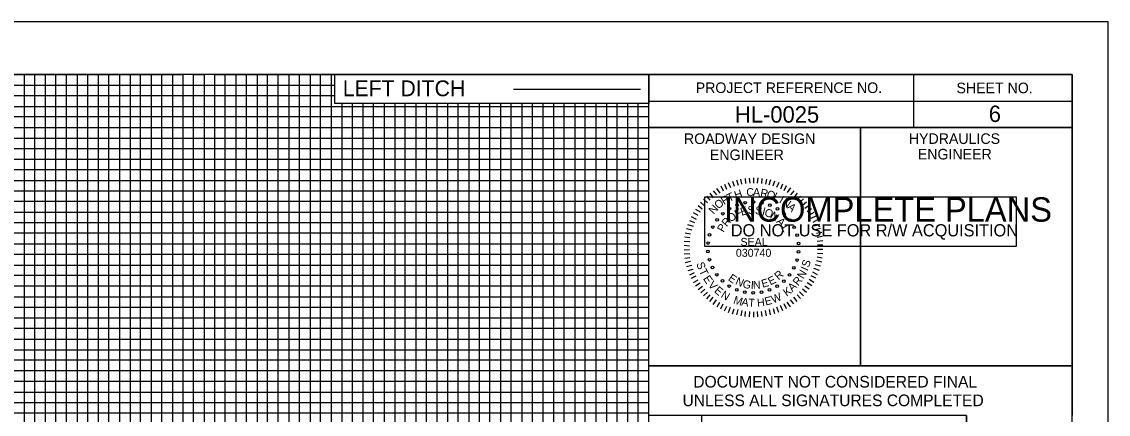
# Model space of a CAD drawing. Extents: x 1524869 to 1526553, y 501099 to 502199.
# Drawn here: x 1526040 to 1526553, y 502013 to 502199 of the extents above; entities that cross this region are included whole.
import ezdxf

# ---------------------------------------------------------------- set-up
doc = ezdxf.new("R2010")
doc.units = 0
for name, color, linetype in [('Old_Level_9', 7, 'Continuous'), ('Prop Grid Mask', 7, 'Continuous'), ('Sheet Data Field CELL', 7, 'Continuous'), ('Sheet Layout Profile Border Port 1', 7, 'Continuous'), ('Sheet Plot Border Outside CELL', 7, 'Continuous'), ('Sheet Profile CELL', 7, 'Continuous'), ('Sheet Profile Grid Major CELL', 7, 'Continuous'), ('Sheet Profile Grid Middle CELL', 7, 'Continuous'), ('Sheet Profile Grid Minor CELL', 7, 'Continuous'), ('Sheet Sticker Exception Certification CELL', 7, 'Continuous'), ('Sheet Sticker Incomplete CELL', 7, 'Continuous')]:
    doc.layers.add(name, color=color, linetype=linetype)

msp = doc.modelspace()

# ---------------------------------------------------------------- linework, layer by layer
at = {"layer": 'Old_Level_9'}
for p, q in [((1526272.11, 502166.74), (1526332.11, 502166.74)), ((1526377.53, 502123.79), (1526378.23, 502121.29)), ((1526379.43, 502124.19), (1526379.93, 502121.79)), ((1526381.53, 502124.49), (1526381.73, 502122.09)), ((1526383.43, 502124.59), (1526383.73, 502122.19)), ((1526385.53, 502124.79), (1526385.53, 502122.19)), ((1526387.63, 502124.79), (1526387.33, 502122.19)), ((1526389.53, 502124.49), (1526389.33, 502122.09)), ((1526391.63, 502124.19), (1526391.13, 502121.79)), ((1526393.53, 502123.79), (1526392.83, 502121.39)), ((1526366.53, 502118.69), (1526368.03, 502116.69)), ((1526368.13, 502119.79), (1526369.63, 502117.59)), ((1526370.03, 502120.99), (1526371.23, 502118.59)), ((1526371.83, 502121.79), (1526372.73, 502119.49)), ((1526373.53, 502122.59), (1526374.73, 502120.19)), ((1526375.63, 502123.19), (1526376.33, 502120.79)), ((1526395.43, 502123.19), (1526394.73, 502120.79)), ((1526397.53, 502122.59), (1526396.33, 502120.19)), ((1526399.23, 502121.79), (1526398.33, 502119.49)), ((1526401.03, 502120.99), (1526399.83, 502118.59)), ((1526402.93, 502119.99), (1526401.43, 502117.79)), ((1526404.53, 502118.69), (1526403.03, 502116.69)), ((1526360.53, 502113.29), (1526362.43, 502111.59)), ((1526361.93, 502114.69), (1526363.73, 502112.99)), ((1526363.33, 502116.19), (1526364.93, 502114.29)), ((1526364.93, 502117.49), (1526366.53, 502115.39)), ((1526406.13, 502117.49), (1526404.53, 502115.49)), ((1526407.73, 502116.19), (1526406.13, 502114.39)), ((1526409.13, 502114.89), (1526407.33, 502112.99)), ((1526410.53, 502113.29), (1526408.63, 502111.69)), ((1526357.03, 502108.39), (1526359.23, 502107.09)), ((1526358.13, 502109.99), (1526360.33, 502108.69)), ((1526359.43, 502111.69), (1526361.33, 502110.09)), ((1526411.83, 502111.69), (1526409.73, 502110.29)), ((1526412.93, 502110.09), (1526410.83, 502108.69)), ((1526414.03, 502108.39), (1526411.83, 502107.09)), ((1526354.43, 502102.79), (1526357.03, 502101.99)), ((1526355.23, 502104.69), (1526357.63, 502103.69)), ((1526356.03, 502106.49), (1526358.43, 502105.29)), ((1526415.03, 502106.59), (1526412.63, 502105.49)), ((1526415.83, 502104.89), (1526413.63, 502103.69)), ((1526416.63, 502102.79), (1526414.03, 502101.99)), ((1526353.33, 502098.79), (1526355.83, 502098.29)), ((1526353.83, 502100.89), (1526356.33, 502100.19)), ((1526417.23, 502100.89), (1526414.73, 502100.19)), ((1526417.73, 502098.99), (1526415.23, 502098.49)), ((1526352.73, 502092.89), (1526355.23, 502092.69)), ((1526352.83, 502094.79), (1526355.43, 502094.69)), ((1526353.03, 502096.89), (1526355.53, 502096.59)), ((1526418.03, 502097.09), (1526415.63, 502096.59)), ((1526418.23, 502094.99), (1526415.63, 502094.69)), ((1526418.33, 502092.89), (1526415.83, 502092.89)), ((1526352.73, 502090.79), (1526355.23, 502090.99)), ((1526352.83, 502088.79), (1526355.43, 502089.09)), ((1526418.33, 502090.99), (1526415.83, 502090.99)), ((1526418.23, 502088.89), (1526415.83, 502089.09)), ((1526353.03, 502086.79), (1526355.53, 502087.19)), ((1526353.33, 502084.79), (1526355.83, 502085.39)), ((1526353.93, 502082.89), (1526356.33, 502083.49)), ((1526417.23, 502082.99), (1526414.73, 502083.69)), ((1526417.73, 502084.89), (1526415.23, 502085.59)), ((1526418.03, 502086.79), (1526415.63, 502087.29)), ((1526354.63, 502080.99), (1526357.03, 502081.69)), ((1526355.43, 502078.99), (1526357.63, 502079.99)), ((1526356.23, 502077.29), (1526358.43, 502078.39)), ((1526415.03, 502077.29), (1526412.83, 502078.39)), ((1526415.83, 502078.99), (1526413.63, 502080.19)), ((1526416.63, 502080.99), (1526414.03, 502081.89)), ((1526357.13, 502075.39), (1526359.43, 502076.59)), ((1526358.13, 502073.79), (1526360.33, 502075.09)), ((1526359.43, 502071.99), (1526361.43, 502073.59)), ((1526360.63, 502070.39), (1526362.53, 502072.19)), ((1526410.53, 502070.59), (1526408.63, 502072.19)), ((1526411.83, 502072.19), (1526409.73, 502073.59)), ((1526413.13, 502073.79), (1526410.83, 502075.19)), ((1526414.03, 502075.39), (1526411.83, 502076.79)), ((1526361.93, 502068.99), (1526363.83, 502070.69)), ((1526363.53, 502067.59), (1526365.13, 502069.49)), ((1526364.93, 502066.29), (1526366.53, 502068.39)), ((1526366.53, 502064.99), (1526368.03, 502067.09)), ((1526404.53, 502065.19), (1526403.03, 502067.19)), ((1526406.23, 502066.29), (1526404.53, 502068.39)), ((1526407.73, 502067.69), (1526406.13, 502069.49)), ((1526409.13, 502068.99), (1526407.33, 502070.89)), ((1526368.33, 502063.89), (1526369.63, 502066.09)), ((1526370.03, 502062.89), (1526371.23, 502065.19)), ((1526371.83, 502061.99), (1526372.93, 502064.19)), ((1526373.73, 502061.19), (1526374.73, 502063.59)), ((1526375.63, 502060.49), (1526376.43, 502062.89)), ((1526377.73, 502060.09), (1526378.23, 502062.49)), ((1526379.63, 502059.59), (1526380.13, 502062.09)), ((1526381.53, 502059.29), (1526381.83, 502061.69)), ((1526383.63, 502059.09), (1526383.73, 502061.69)), ((1526387.63, 502059.09), (1526387.43, 502061.69)), ((1526389.63, 502059.29), (1526389.33, 502061.69)), ((1526391.73, 502059.59), (1526391.23, 502062.09)), ((1526393.63, 502060.09), (1526393.03, 502062.49)), ((1526395.53, 502060.49), (1526394.93, 502062.89)), ((1526397.53, 502061.19), (1526396.53, 502063.69)), ((1526399.43, 502061.99), (1526398.33, 502064.39)), ((1526401.13, 502062.89), (1526400.03, 502065.19)), ((1526402.93, 502063.89), (1526401.43, 502066.09)), ((1526385.73, 502058.99), (1526385.73, 502061.49))]:
    msp.add_line(p, q, dxfattribs=at)
for centre in [(1526381.58, 502113.03), (1526385.53, 502113.38), (1526389.48, 502113), (1526371.03, 502107.83), (1526374.2, 502110.2), (1526377.76, 502111.96), (1526393.29, 502111.9), (1526396.83, 502110.12), (1526399.98, 502107.71), (1526368.35, 502104.91), (1526402.64, 502104.77), (1526364.8, 502097.85), (1526366.25, 502101.54), (1526404.72, 502101.39), (1526406.13, 502097.69), (1526364.05, 502093.96), (1526406.85, 502093.79), (1526364.04, 502089.99), (1526406.83, 502089.82), (1526364.75, 502086.09), (1526366.17, 502082.39), (1526404.64, 502082.24), (1526406.09, 502085.93), (1526368.25, 502079.01), (1526402.54, 502078.87), (1526370.91, 502076.07), (1526374.06, 502073.66), (1526377.6, 502071.88), (1526393.13, 502071.82), (1526396.68, 502073.58), (1526399.86, 502075.95), (1526381.41, 502070.78), (1526385.36, 502070.4), (1526389.31, 502070.75)]:
    msp.add_circle(centre, 0.63, dxfattribs=at)
at = {"layer": 'Prop Grid Mask'}
for p, q in [((1526187.87, 502173.56), (1526336.08, 502173.56)), ((1526187.87, 502159.84), (1526187.87, 502173.56)), ((1526336.08, 502173.56), (1526336.08, 502159.84)), ((1526336.08, 502159.84), (1526187.87, 502159.84))]:
    msp.add_line(p, q, dxfattribs=at)
at = {"layer": 'Sheet Layout Profile Border Port 1'}
msp.add_lwpolyline([(1525086.08, 502173.56), (1525058.64, 501673.56), (1526486.08, 501673.56), (1526486.08, 502012.51), (1526336.03, 502012.51), (1526336.08, 502173.56)], close=True, dxfattribs=at)
msp.add_lwpolyline([(1525086.08, 502173.56), (1525058.64, 501673.56), (1526486.08, 501673.56), (1526486.08, 502012.51), (1526336.03, 502012.51), (1526336.08, 502173.56)], close=True, dxfattribs=at)
at = {"layer": 'Sheet Plot Border Outside CELL'}
msp.add_lwpolyline([(1524869.08, 501098.56), (1526553.08, 501098.56), (1526553.08, 502198.56), (1524869.08, 502198.56)], close=True, dxfattribs=at)
at = {"layer": 'Sheet Profile CELL'}
for p, q in [((1526461.08, 502173.51), (1526461.08, 502148.51)), ((1526336.03, 502161.01), (1526536.08, 502161.01)), ((1526436.08, 502148.51), (1526436.08, 502036.06))]:
    msp.add_line(p, q, dxfattribs=at)
for points in [[(1526536.08, 502173.56), (1525036.08, 502173.56), (1525036.08, 501123.56), (1526536.08, 501123.56)], [(1526336.03, 502173.56), (1526536.08, 502173.56), (1526536.08, 502148.51), (1526336.03, 502148.51)], [(1526336.03, 502148.51), (1526436.08, 502148.51), (1526436.08, 502036.01), (1526336.03, 502036.01)], [(1526436.08, 502148.51), (1526536.08, 502148.51), (1526536.08, 502036.01), (1526436.08, 502036.01)]]:
    msp.add_lwpolyline(points, close=True, dxfattribs=at)
at = {"layer": 'Sheet Profile Grid Major CELL'}
for points in [[(1526036.08, 502173.56), (1526086.08, 502173.56), (1526086.08, 501673.56), (1526136.08, 501673.56), (1526136.08, 502173.56), (1526186.08, 502173.56), (1526186.08, 501673.56), (1526236.08, 501673.56), (1526236.08, 502159.84)], [(1526286.08, 502159.84), (1526286.08, 501673.56), (1526336.08, 501673.56), (1526336.08, 502173.56), (1526362.38, 502173.56)], [(1525036.08, 502123.56), (1526336.08, 502123.56)], [(1526336.08, 502073.56), (1525036.08, 502073.56), (1525036.08, 502023.56), (1526336.08, 502023.56)], [(1526486.08, 502012.51), (1526486.08, 501673.56), (1526536.08, 501673.56), (1526536.08, 502023.56)]]:
    msp.add_lwpolyline(points, dxfattribs=at)
at = {"layer": 'Sheet Profile Grid Middle CELL'}
msp.add_line((1525036.08, 502148.56), (1526336.03, 502148.56), dxfattribs=at)
for points in [[(1526011.08, 501673.56), (1526061.08, 501673.56), (1526061.08, 502173.56), (1526111.08, 502173.56), (1526111.08, 501673.56), (1526161.08, 501673.56), (1526161.08, 502173.56), (1526211.08, 502173.56)], [(1526211.08, 502159.84), (1526211.08, 501673.56), (1526261.08, 501673.56), (1526261.08, 502159.84)], [(1526311.08, 502159.84), (1526311.08, 501673.56), (1526361.08, 501673.56), (1526361.08, 502012.51)], [(1526336.08, 502098.56), (1525036.08, 502098.56), (1525036.08, 502048.56), (1526336.08, 502048.56)]]:
    msp.add_lwpolyline(points, dxfattribs=at)
at = {"layer": 'Sheet Profile Grid Minor CELL'}
for p, q in [((1525086.08, 502168.56), (1526187.87, 502168.56)), ((1526187.87, 502163.52), (1525086.08, 502163.21)), ((1525086.08, 502158.56), (1526336.08, 502158.56)), ((1526336.03, 502038.56), (1525086.08, 502038.56)), ((1526336.08, 502033.56), (1525086.08, 502033.56)), ((1526336.08, 502028.56), (1525086.08, 502028.56)), ((1525086.08, 502018.56), (1526336.08, 502018.56)), ((1526336.08, 502013.56), (1525086.08, 502013.56))]:
    msp.add_line(p, q, dxfattribs=at)
for points in [[(1526031.08, 502173.56), (1526041.08, 502173.56), (1526041.08, 501673.56)], [(1526046.08, 501673.56), (1526046.08, 502173.56), (1526051.08, 502173.56), (1526051.08, 501673.56)], [(1526056.08, 501673.56), (1526056.08, 502173.56), (1526066.08, 502173.56), (1526066.08, 501673.56)], [(1526071.08, 501673.56), (1526071.08, 502173.56), (1526076.08, 502173.56), (1526076.08, 501673.56)], [(1526081.08, 501673.56), (1526081.08, 502173.56), (1526091.08, 502173.56), (1526091.08, 501673.56)], [(1526096.08, 501673.56), (1526096.08, 502173.56), (1526101.08, 502173.56), (1526101.08, 501673.56)], [(1526106.08, 501673.56), (1526106.08, 502173.56), (1526116.08, 502173.56), (1526116.08, 501673.56)], [(1526121.08, 501673.56), (1526121.08, 502173.56), (1526126.08, 502173.56), (1526126.08, 501673.56)], [(1526131.08, 501673.56), (1526131.08, 502173.56), (1526141.08, 502173.56), (1526141.08, 501673.56)], [(1526146.08, 501673.56), (1526146.08, 502173.56), (1526151.08, 502173.56), (1526151.08, 501673.56)], [(1526156.08, 501673.56), (1526156.08, 502173.56), (1526166.08, 502173.56), (1526166.08, 501673.56)], [(1526171.08, 501673.56), (1526171.08, 502173.56), (1526176.08, 502173.56), (1526176.08, 501673.56)], [(1526181.08, 501673.56), (1526181.08, 502173.56), (1526191.08, 502173.56)], [(1526191.08, 502159.84), (1526191.08, 501673.56), (1526196.08, 501673.56), (1526196.08, 502159.84)], [(1526201.08, 502159.84), (1526201.08, 501673.56), (1526206.08, 501673.56), (1526206.08, 502159.84)], [(1526216.08, 502159.84), (1526216.08, 501673.56), (1526221.08, 501673.56), (1526221.08, 502159.84)], [(1526226.08, 501673.56), (1526231.08, 501673.56), (1526231.08, 502159.84)], [(1526226.08, 502159.84), (1526226.08, 501673.56)], [(1526241.08, 502159.84), (1526241.08, 501673.56), (1526246.08, 501673.56), (1526246.08, 502159.84)], [(1526251.08, 502159.84), (1526251.08, 501673.56), (1526256.08, 501673.56), (1526256.08, 502159.84)], [(1526266.08, 502159.84), (1526266.08, 501673.56), (1526271.08, 501673.56), (1526271.08, 502159.84)], [(1526276.08, 502159.84), (1526276.08, 501673.56), (1526281.08, 501673.56), (1526281.08, 502159.84)], [(1526291.08, 502159.84), (1526291.08, 501673.56), (1526296.08, 501673.56), (1526296.08, 502159.84)], [(1526301.08, 502159.84), (1526301.08, 501673.56), (1526306.08, 501673.56), (1526306.08, 502159.84)], [(1526316.08, 502159.84), (1526316.08, 501673.56), (1526321.08, 501673.56), (1526321.08, 502159.84)], [(1526326.08, 502159.84), (1526326.08, 501673.56), (1526331.08, 501673.56), (1526331.08, 502159.84)], [(1526336.08, 502153.56), (1525086.08, 502153.56), (1525086.08, 502143.56), (1526336.08, 502143.56)], [(1526336.03, 502138.56), (1525086.08, 502138.56), (1525086.08, 502133.56), (1526336.08, 502133.56)], [(1526336.08, 502128.56), (1525086.08, 502128.56), (1525086.08, 502118.56), (1526336.08, 502118.56)], [(1526336.08, 502113.56), (1525086.08, 502113.56), (1525086.08, 502108.56), (1526336.08, 502108.56)], [(1526336.08, 502103.56), (1525086.08, 502103.56), (1525086.08, 502093.56), (1526336.08, 502093.56)], [(1526336.08, 502088.56), (1525086.08, 502088.56), (1525086.08, 502083.56), (1526336.08, 502083.56)], [(1526336.08, 502078.56), (1525086.08, 502078.56), (1525086.08, 502068.56), (1526336.08, 502068.56)], [(1526336.08, 502063.46), (1525086.18, 502063.46), (1525086.18, 502058.56), (1526336.08, 502058.56)], [(1526336.08, 502053.56), (1525086.08, 502053.56), (1525086.08, 502043.56), (1526336.08, 502043.56)]]:
    msp.add_lwpolyline(points, dxfattribs=at)
at = {"layer": 'Sheet Sticker Exception Certification CELL'}
for p, q in [((1526336.03, 502012.51), (1526336.03, 502036.01)), ((1526336.03, 502036.01), (1526536.07, 502036.01)), ((1526336.03, 502012.51), (1526336.03, 502036.01)), ((1526336.03, 502036.01), (1526536.07, 502036.01)), ((1526536.07, 502036), (1526536.07, 502012.5)), ((1526536.07, 502036), (1526536.07, 502012.5))]:
    msp.add_line(p, q, dxfattribs=at)
at = {"layer": 'Sheet Sticker Incomplete CELL'}
msp.add_lwpolyline([(1526362.6, 502092.36), (1526362.6, 502115.86), (1526509.6, 502115.86), (1526509.6, 502092.36)], close=True, dxfattribs=at)

# ---------------------------------------------------------------- texts
at = {"layer": 'Old_Level_9'}
for s, height, p in [('LEFT DITCH', 7.485, (1526191.56, 502163.34)), ('SEAL', 3.759, (1526379.39, 502092.63)), ('030740', 3.759, (1526377.19, 502087.47))]:
    msp.add_text(s, height=height, dxfattribs=at).set_placement(p)
for s, height, rotation, p in [('H', 3.78, 17.7433, (1526377.13, 502114.69)), ('C', 3.78, 4.9399, (1526382.33, 502115.99)), ('A', 3.78, 357.9749, (1526385.23, 502116.19)), ('R', 3.78, 350.0216, (1526388.53, 502115.99)), ('O', 3.78, 343.0868, (1526391.43, 502115.49)), ('O', 3.78, 39.9442, (1526368.93, 502109.79)), ('R', 3.78, 32.1754, (1526371.63, 502111.89)), ('T', 3.78, 25.4358, (1526374.03, 502113.29)), ('L', 3.78, 335.7459, (1526394.43, 502114.59)), ('I', 3.78, 330.806, (1526397.33, 502113.19)), ('N', 3.78, 324.9038, (1526398.63, 502112.49)), ('N', 3.78, 48.0667, (1526366.73, 502107.29)), ('O', 3.76, 38.2518, (1526374.83, 502103.59)), ('F', 3.76, 26.4, (1526377.73, 502105.69)), ('E', 3.76, 16.5889, (1526379.93, 502106.79)), ('S', 3.76, 4.468, (1526382.93, 502107.59)), ('S', 3.76, 353.0415, (1526386.13, 502107.69)), ('I', 3.76, 345.4821, (1526389.33, 502107.29)), ('O', 3.76, 337.8749, (1526390.33, 502107.09)), ('N', 3.76, 327.393, (1526393.03, 502105.99)), ('A', 3.78, 317.0051, (1526401.13, 502110.59)), ('P', 3.76, 60.1236, (1526371.33, 502098.79)), ('R', 3.76, 49.7478, (1526372.93, 502101.39)), ('A', 3.76, 313.9438, (1526396.03, 502103.89)), ('L', 3.76, 301.5323, (1526398.43, 502101.19)), ('S', 3.78, 288.212, (1526358.48, 502084.31)), ('T', 3.78, 295.6244, (1526359.67, 502080.79)), ('I', 3.78, 66.0464, (1526411.01, 502080.51)), ('S', 3.78, 72.2579, (1526411.71, 502082.2)), ('E', 3.78, 303.8225, (1526361.54, 502077.11)), ('E', 3.76, 324.8692, (1526373.23, 502076.59)), ('N', 3.76, 336.0584, (1526376.63, 502074.59)), ('E', 3.76, 15.8057, (1526389.83, 502072.79)), ('E', 3.76, 27.1568, (1526393.53, 502073.89)), ('R', 3.76, 40.3493, (1526397.33, 502076.29)), ('R', 3.78, 51.1503, (1526406.62, 502073.47)), ('N', 3.78, 59.3726, (1526409.08, 502076.71)), ('V', 3.78, 311.9298, (1526363.8, 502073.93)), ('E', 3.78, 320.2312, (1526366.69, 502070.96)), ('G', 3.76, 347.4812, (1526380.13, 502072.99)), ('I', 3.76, 355.6246, (1526384.13, 502072.29)), ('N', 3.76, 3.1278, (1526385.33, 502072.29)), ('K', 3.78, 36.141, (1526401.23, 502068.53)), ('A', 3.78, 43.5217, (1526403.86, 502070.8)), ('N', 3.78, 328.329, (1526369.82, 502068.53)), ('M', 3.78, 342.337, (1526375.73, 502065.53)), ('A', 3.78, 350.1822, (1526379.62, 502064.5)), ('T', 3.78, 357.3866, (1526383.03, 502063.94)), ('H', 3.78, 6.0112, (1526387.38, 502063.83)), ('E', 3.78, 14.1648, (1526391.32, 502064.41)), ('W', 3.78, 22.0058, (1526394.78, 502065.37))]:
    msp.add_text(s, height=height, rotation=rotation, dxfattribs=at).set_placement(p)
at = {"layer": 'Sheet Data Field CELL'}
for s, p in [('HL-0025', (1526376.78, 502150.87)), ('6', (1526496.64, 502151.17))]:
    msp.add_text(s, height=7.75, dxfattribs=at).set_placement(p)
at = {"layer": 'Sheet Profile CELL'}
for s, height, p in [('PROJECT REFERENCE NO.', 5.0001, (1526358.24, 502164.87)), ('SHEET NO.', 5, (1526481.39, 502164.77)), ('ROADWAY DESIGN', 5.0001, (1526352.69, 502140.77)), ('HYDRAULICS', 5, (1526458.89, 502140.82)), ('ENGINEER', 5, (1526364.94, 502133.17)), ('ENGINEER', 5, (1526463.14, 502133.47))]:
    msp.add_text(s, height=height, dxfattribs=at).set_placement(p)
at = {"layer": 'Sheet Sticker Exception Certification CELL'}
for s, p in [('DOCUMENT NOT CONSIDERED FINAL', (1526357.1, 502025.67)), ('DOCUMENT NOT CONSIDERED FINAL', (1526357.1, 502025.67)), ('UNLESS ALL SIGNATURES COMPLETED', (1526352.03, 502016.87)), ('UNLESS ALL SIGNATURES COMPLETED', (1526352.03, 502016.87))]:
    msp.add_text(s, height=5.5, dxfattribs=at).set_placement(p)
at = {"layer": 'Sheet Sticker Incomplete CELL'}
for s, height, p in [('INCOMPLETE PLANS', 11.52, (1526371.55, 502104.06)), ('DO NOT USE FOR R/W ACQUISITION', 5.76, (1526374.8, 502097.11))]:
    msp.add_text(s, height=height, dxfattribs=at).set_placement(p)

doc.saveas('drawing.dxf')
